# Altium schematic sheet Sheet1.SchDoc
size A4
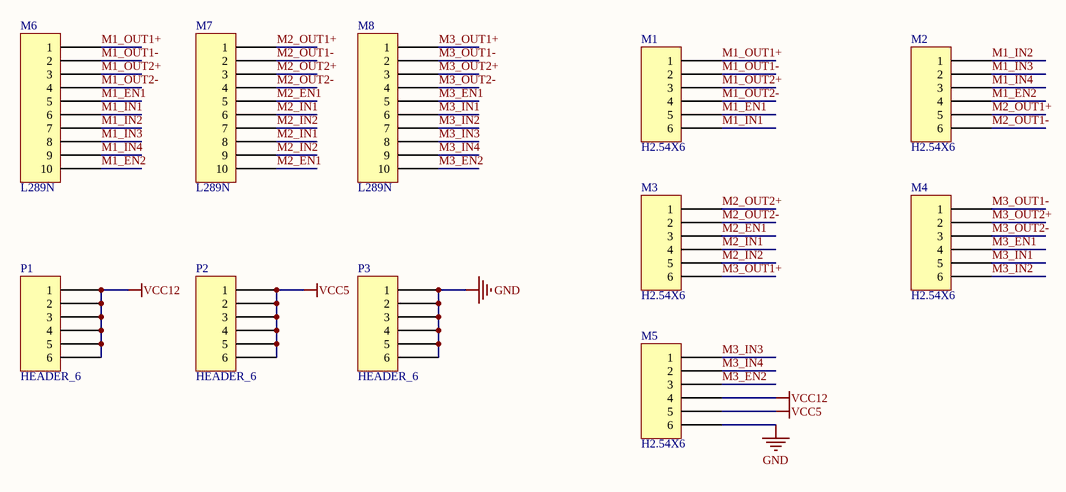
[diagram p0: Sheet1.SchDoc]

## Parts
M1  H2.54X6  [Header6]
M2  H2.54X6  [Header6]
M3  H2.54X6  [Header6]
M4  H2.54X6  [Header6]
M5  H2.54X6  [Header6]
M6  L289N  [HDR1X10]
M7  L289N  [HDR1X10]
M8  L289N  [HDR1X10]
P1  HEADER_6  [HDR1X6]
P2  HEADER_6  [HDR1X6]
P3  HEADER_6  [HDR1X6]

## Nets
GND: M5.6 P3.1 P3.2 P3.3 P3.4 P3.5 P3.6
VCC5: M5.5 P2.1 P2.2 P2.3 P2.4 P2.5 P2.6
VCC12: M5.4 P1.1 P1.2 P1.3 P1.4 P1.5 P1.6
M1_EN1: M1.5 M6.5
M1_EN2: M2.4 M6.10
M1_IN1: M1.6 M6.6
M1_IN2: M2.1 M6.7
M1_IN3: M2.2 M6.8
M1_IN4: M2.3 M6.9
M1_OUT1+: M1.1 M6.1
M1_OUT1-: M1.2 M6.2
M1_OUT2+: M1.3 M6.3
M1_OUT2-: M1.4 M6.4
M2_EN1: M3.3 M7.5 M7.10
M2_IN1: M3.4 M7.6 M7.8
M2_IN2: M3.5 M7.7 M7.9
M2_OUT1+: M2.5 M7.1
M2_OUT1-: M2.6 M7.2
M2_OUT2+: M3.1 M7.3
M2_OUT2-: M3.2 M7.4
M3_EN1: M4.4 M8.5
M3_EN2: M5.3 M8.10
M3_IN1: M4.5 M8.6
M3_IN2: M4.6 M8.7
M3_IN3: M5.1 M8.8
M3_IN4: M5.2 M8.9
M3_OUT1+: M3.6 M8.1
M3_OUT1-: M4.1 M8.2
M3_OUT2+: M4.2 M8.3
M3_OUT2-: M4.3 M8.4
